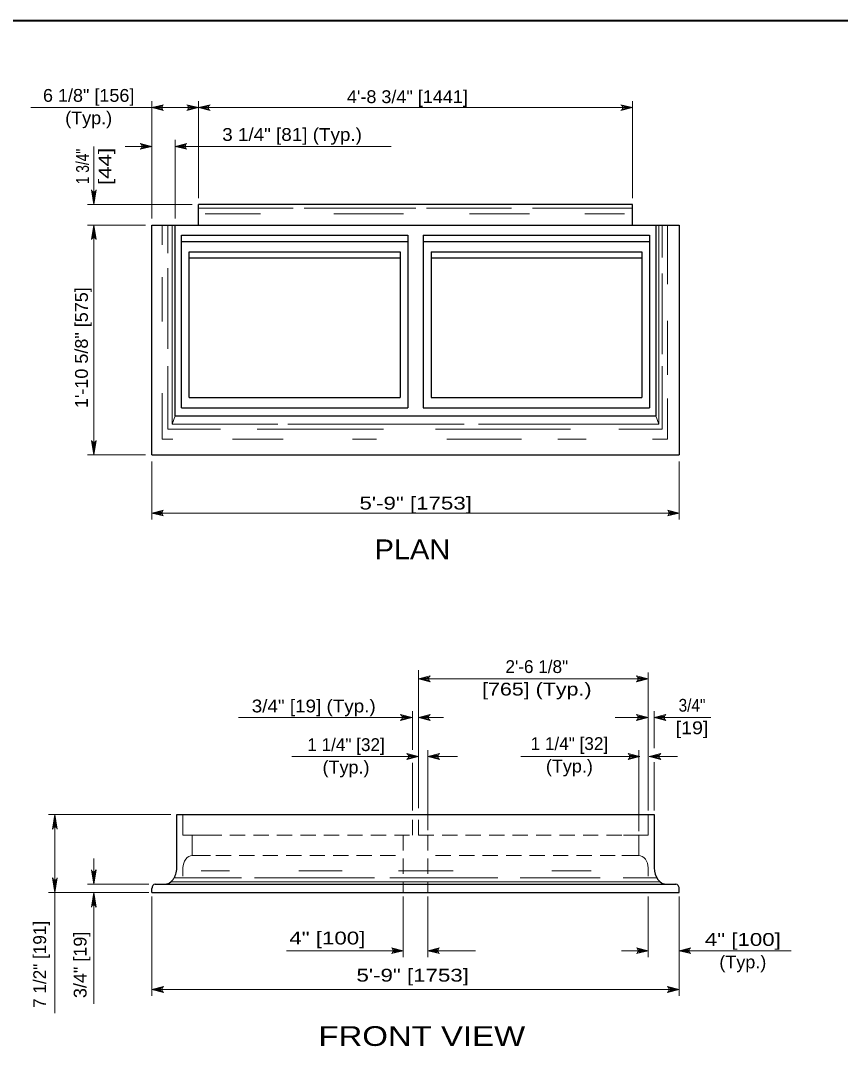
# Model space of a CAD drawing. Extents: x 1352.5 to 1386.5, y 735.9 to 779.9.
# Drawn here: x 1365.77 to 1375.75, y 744.93 to 757.42 of the extents above; entities that cross this region are included whole.
import ezdxf
from ezdxf.enums import TextEntityAlignment as Align

# ---------------------------------------------------------------- set-up
doc = ezdxf.new("R2010")
doc.units = 0
doc.header["$LTSCALE"] = 0.062
doc.linetypes.add('MEDIUM_DASHED', pattern=[4.5, 3, -1.5])
doc.layers.add('1', color=7, linetype='Continuous', lineweight=13)

msp = doc.modelspace()

# ---------------------------------------------------------------- linework, layer by layer
at = {"layer": '1', "lineweight": 25}
for p, q in [((1354.513, 757.41967), (1386.013, 757.41967)), ((1367.93525, 754.92942), (1367.93525, 755.17925)), ((1367.65208, 752.60575), (1367.65208, 754.92942)), ((1373.50492, 754.92942), (1373.50492, 752.60575)), ((1367.72758, 752.70567), (1367.72758, 754.80442)), ((1367.72758, 754.80442), (1370.48408, 754.80442)), ((1367.72758, 754.7295), (1370.48408, 754.7295)), ((1370.48408, 754.80442), (1370.48408, 752.70567)), ((1370.67292, 754.80442), (1370.67292, 752.70567)), ((1370.67292, 754.80442), (1373.42933, 754.80442)), ((1370.67292, 754.7295), (1373.42933, 754.7295)), ((1373.42933, 754.80442), (1373.42933, 752.70567)), ((1367.822, 752.83058), (1367.822, 754.60458)), ((1367.822, 754.60458), (1370.38967, 754.60458)), ((1370.38967, 754.60458), (1370.38967, 752.83058)), ((1370.76725, 754.60458), (1370.76725, 752.83058)), ((1370.76725, 754.60458), (1373.335, 754.60458)), ((1373.335, 754.60458), (1373.335, 752.83058)), ((1367.822, 754.52958), (1370.38967, 754.52958)), ((1370.76725, 754.52958), (1373.335, 754.52958)), ((1367.822, 752.83058), (1370.38967, 752.83058)), ((1370.76725, 752.83058), (1373.335, 752.83058)), ((1367.65208, 752.60575), (1373.50492, 752.60575)), ((1367.72758, 752.70567), (1370.48408, 752.70567)), ((1370.67292, 752.70567), (1373.42933, 752.70567)), ((1367.36892, 752.131), (1373.78808, 752.131)), ((1367.40667, 746.90283), (1373.75033, 746.90283)), ((1367.36892, 746.80292), (1367.36892, 746.85283)), ((1367.36892, 746.80292), (1373.78808, 746.80292)), ((1373.78808, 746.80292), (1373.78808, 746.85283))]:
    msp.add_line(p, q, dxfattribs=at)
at = {"layer": '1'}
for p, q in [((1367.36892, 756.35925), (1365.89425, 756.35925)), ((1367.36892, 755.00808), (1367.36892, 756.43792)), ((1367.49708, 756.38167), (1367.36892, 756.35925)), ((1367.49275, 756.37058), (1367.36892, 756.35925)), ((1367.49142, 756.35925), (1367.36892, 756.35925)), ((1367.49367, 756.34483), (1367.36892, 756.35925)), ((1367.49858, 756.3345), (1367.36892, 756.35925)), ((1373.22167, 756.35925), (1367.36892, 756.35925)), ((1367.7065, 756.35925), (1367.93525, 756.35925)), ((1367.80558, 756.3345), (1367.93525, 756.35925)), ((1367.80708, 756.38167), (1367.93525, 756.35925)), ((1367.8105, 756.34483), (1367.93525, 756.35925)), ((1367.81142, 756.37058), (1367.93525, 756.35925)), ((1367.81275, 756.35925), (1367.93525, 756.35925)), ((1367.93525, 755.25792), (1367.93525, 756.43792)), ((1368.0635, 756.38167), (1367.93525, 756.35925)), ((1368.05917, 756.37058), (1367.93525, 756.35925)), ((1368.05783, 756.35925), (1367.93525, 756.35925)), ((1368.06008, 756.34483), (1367.93525, 756.35925)), ((1368.065, 756.3345), (1367.93525, 756.35925)), ((1373.092, 756.3345), (1373.22167, 756.35925)), ((1373.0935, 756.38167), (1373.22167, 756.35925)), ((1373.09692, 756.34483), (1373.22167, 756.35925)), ((1373.09783, 756.37058), (1373.22167, 756.35925)), ((1373.09917, 756.35925), (1373.22167, 756.35925)), ((1373.22167, 755.25792), (1373.22167, 756.43792)), ((1366.66092, 755.17925), (1366.66092, 755.88725)), ((1366.66092, 755.17925), (1366.66092, 755.88725)), ((1367.36892, 755.88725), (1367.04092, 755.88725)), ((1367.23917, 755.8625), (1367.36892, 755.88725)), ((1367.24067, 755.90967), (1367.36892, 755.88725)), ((1367.24408, 755.87283), (1367.36892, 755.88725)), ((1367.245, 755.89858), (1367.36892, 755.88725)), ((1367.24633, 755.88725), (1367.36892, 755.88725)), ((1367.65208, 755.00808), (1367.65208, 755.96592)), ((1367.78025, 755.90967), (1367.65208, 755.88725)), ((1367.77592, 755.89858), (1367.65208, 755.88725)), ((1367.77458, 755.88725), (1367.65208, 755.88725)), ((1367.77692, 755.87283), (1367.65208, 755.88725)), ((1367.78175, 755.8625), (1367.65208, 755.88725)), ((1370.283, 755.88725), (1367.65208, 755.88725)), ((1366.64292, 755.3395), (1366.66092, 755.17925)), ((1366.65183, 755.33408), (1366.66092, 755.17925)), ((1366.68067, 755.34133), (1366.66092, 755.17925)), ((1366.67242, 755.33525), (1366.66092, 755.17925)), ((1366.66092, 755.33242), (1366.66092, 755.17925)), ((1367.85658, 755.17925), (1366.58225, 755.17925)), ((1369.08867, 755.13342), (1367.93525, 755.13342)), ((1370.58075, 755.13342), (1369.22075, 755.13342)), ((1371.748, 755.13342), (1370.71292, 755.13342)), ((1373.22167, 755.13342), (1372.00133, 755.13342)), ((1368.69217, 755.06783), (1368.01492, 755.06783)), ((1370.43208, 755.06783), (1369.58417, 755.06783)), ((1371.96833, 755.06783), (1371.236, 755.06783)), ((1373.12458, 755.06783), (1372.64008, 755.06783)), ((1367.29025, 754.92942), (1366.58225, 754.92942)), ((1366.64108, 754.76725), (1366.66092, 754.92942)), ((1366.64933, 754.77342), (1366.66092, 754.92942)), ((1366.66092, 754.77625), (1366.66092, 754.92942)), ((1366.66992, 754.77458), (1366.66092, 754.92942)), ((1366.67883, 754.76917), (1366.66092, 754.92942)), ((1366.66092, 752.131), (1366.66092, 754.92942)), ((1367.49183, 754.68892), (1367.49183, 754.92942)), ((1367.5635, 754.58692), (1367.5635, 754.92942)), ((1367.61433, 752.50575), (1367.61433, 754.92942)), ((1373.54267, 754.92942), (1373.54267, 752.50575)), ((1373.58158, 754.92942), (1373.58158, 754.53583)), ((1373.64758, 754.92942), (1373.64758, 754.208)), ((1367.5635, 753.421), (1367.5635, 754.40475)), ((1367.49183, 753.75625), (1367.49183, 754.29542)), ((1373.58158, 754.33917), (1373.58158, 753.35542)), ((1373.64758, 753.7635), (1373.64758, 753.10767)), ((1367.5635, 752.44467), (1367.5635, 753.20975)), ((1373.58158, 753.20975), (1373.58158, 752.44467)), ((1367.49183, 752.32075), (1367.49183, 752.88183)), ((1373.64758, 752.81625), (1373.64758, 752.32075)), ((1367.61433, 752.50575), (1367.65208, 752.60575)), ((1373.50492, 752.60575), (1373.54267, 752.50575)), ((1367.61433, 752.50575), (1368.90142, 752.50575)), ((1369.02258, 752.50575), (1371.16992, 752.50575)), ((1371.34608, 752.50575), (1373.54267, 752.50575)), ((1367.5635, 752.44467), (1368.20217, 752.44467)), ((1368.64817, 752.44467), (1370.18983, 752.44467)), ((1370.823, 752.44467), (1372.46383, 752.44467)), ((1373.05292, 752.44467), (1373.58158, 752.44467)), ((1366.64292, 752.29125), (1366.66092, 752.131)), ((1366.65183, 752.28583), (1366.66092, 752.131)), ((1366.68067, 752.29317), (1366.66092, 752.131)), ((1366.67242, 752.287), (1366.66092, 752.131)), ((1366.66092, 752.28417), (1366.66092, 752.131)), ((1367.49183, 752.32075), (1367.624, 752.32075)), ((1368.35083, 752.32075), (1368.9675, 752.32075)), ((1369.80992, 752.32075), (1370.10175, 752.32075)), ((1370.96067, 752.32075), (1371.86917, 752.32075)), ((1372.30967, 752.32075), (1372.6565, 752.32075)), ((1373.46592, 752.32075), (1373.64758, 752.32075)), ((1367.29025, 752.131), (1366.58225, 752.131)), ((1367.36892, 752.05233), (1367.36892, 751.34433)), ((1373.78808, 752.05233), (1373.78808, 751.34433)), ((1367.49708, 751.44542), (1367.36892, 751.423)), ((1367.49275, 751.43433), (1367.36892, 751.423)), ((1367.49142, 751.423), (1367.36892, 751.423)), ((1367.49367, 751.40858), (1367.36892, 751.423)), ((1367.49858, 751.39825), (1367.36892, 751.423)), ((1367.36892, 751.423), (1373.78808, 751.423)), ((1373.65842, 751.39825), (1373.78808, 751.423)), ((1373.65992, 751.44542), (1373.78808, 751.423)), ((1373.66325, 751.40858), (1373.78808, 751.423)), ((1373.66425, 751.43433), (1373.78808, 751.423)), ((1373.66558, 751.423), (1373.78808, 751.423)), ((1370.61625, 747.82967), (1370.61625, 749.51125)), ((1373.4105, 747.80233), (1373.4105, 749.483)), ((1370.74442, 749.42675), (1370.61625, 749.40433)), ((1370.74008, 749.41567), (1370.61625, 749.40433)), ((1370.61625, 749.40433), (1373.4105, 749.40433)), ((1370.73875, 749.40433), (1370.61625, 749.40433)), ((1370.741, 749.38992), (1370.61625, 749.40433)), ((1370.74592, 749.3795), (1370.61625, 749.40433)), ((1373.28075, 749.3795), (1373.4105, 749.40433)), ((1373.28225, 749.42675), (1373.4105, 749.40433)), ((1373.28567, 749.38992), (1373.4105, 749.40433)), ((1373.28667, 749.41567), (1373.4105, 749.40433)), ((1373.28792, 749.40433), (1373.4105, 749.40433)), ((1370.54075, 748.54208), (1370.54075, 749.01225)), ((1373.486, 748.56075), (1373.486, 749.01225)), ((1370.53858, 748.93358), (1368.42342, 748.93358)), ((1370.40892, 748.90875), (1370.53858, 748.93358)), ((1370.41042, 748.956), (1370.53858, 748.93358)), ((1370.41383, 748.91917), (1370.53858, 748.93358)), ((1370.41475, 748.94492), (1370.53858, 748.93358)), ((1370.41608, 748.93358), (1370.53858, 748.93358)), ((1370.74233, 748.956), (1370.61417, 748.93358)), ((1370.738, 748.94492), (1370.61417, 748.93358)), ((1370.73667, 748.93358), (1370.61417, 748.93358)), ((1370.73892, 748.91917), (1370.61417, 748.93358)), ((1370.74383, 748.90875), (1370.61417, 748.93358)), ((1370.61417, 748.93358), (1370.91725, 748.93358)), ((1373.41058, 748.93358), (1373.01058, 748.93358)), ((1373.28092, 748.90875), (1373.41058, 748.93358)), ((1373.28242, 748.956), (1373.41058, 748.93358)), ((1373.28583, 748.91917), (1373.41058, 748.93358)), ((1373.28675, 748.94492), (1373.41058, 748.93358)), ((1373.28808, 748.93358), (1373.41058, 748.93358)), ((1373.61433, 748.956), (1373.48608, 748.93358)), ((1373.61, 748.94492), (1373.48608, 748.93358)), ((1373.48608, 748.93358), (1374.17425, 748.93358)), ((1373.60867, 748.93358), (1373.48608, 748.93358)), ((1373.61092, 748.91917), (1373.48608, 748.93358)), ((1373.61583, 748.90875), (1373.48608, 748.93358)), ((1370.48808, 748.48058), (1370.61625, 748.45817)), ((1370.7295, 747.5635), (1370.7295, 748.53683)), ((1370.85775, 748.48058), (1370.7295, 748.45817)), ((1373.18167, 748.48058), (1373.30983, 748.45817)), ((1373.29717, 747.55033), (1373.29717, 748.53683)), ((1373.55133, 748.48058), (1373.42317, 748.45817)), ((1370.61625, 748.45817), (1369.07292, 748.45817)), ((1370.4865, 748.43342), (1370.61625, 748.45817)), ((1370.49142, 748.44375), (1370.61625, 748.45817)), ((1370.49242, 748.4695), (1370.61625, 748.45817)), ((1370.49375, 748.45817), (1370.61625, 748.45817)), ((1370.54075, 747.80233), (1370.54075, 748.38358)), ((1370.85333, 748.4695), (1370.7295, 748.45817)), ((1370.85208, 748.45817), (1370.7295, 748.45817)), ((1370.85433, 748.44375), (1370.7295, 748.45817)), ((1370.85925, 748.43342), (1370.7295, 748.45817)), ((1370.7295, 748.45817), (1371.08908, 748.45817)), ((1373.30983, 748.45817), (1371.86042, 748.45817)), ((1373.18017, 748.43342), (1373.30983, 748.45817)), ((1373.18508, 748.44375), (1373.30983, 748.45817)), ((1373.186, 748.4695), (1373.30983, 748.45817)), ((1373.18733, 748.45817), (1373.30983, 748.45817)), ((1373.547, 748.4695), (1373.42317, 748.45817)), ((1373.54567, 748.45817), (1373.42317, 748.45817)), ((1373.54792, 748.44375), (1373.42317, 748.45817)), ((1373.55283, 748.43342), (1373.42317, 748.45817)), ((1373.42317, 748.45817), (1373.76833, 748.45817)), ((1373.486, 747.80233), (1373.486, 748.38825)), ((1367.59825, 747.75233), (1366.10883, 747.75233)), ((1366.16767, 747.59025), (1366.1875, 747.75233)), ((1366.176, 747.59633), (1366.1875, 747.75233)), ((1366.1875, 747.59917), (1366.1875, 747.75233)), ((1366.19658, 747.5975), (1366.1875, 747.75233)), ((1366.20542, 747.59208), (1366.1875, 747.75233)), ((1373.4105, 747.75233), (1373.4105, 747.5025)), ((1373.4105, 747.5025), (1373.11075, 747.5025)), ((1373.29717, 747.5025), (1373.29717, 747.25267)), ((1367.85975, 747.25267), (1368.08108, 747.25267)), ((1373.29717, 747.25267), (1373.08992, 747.25267)), ((1366.65958, 746.90283), (1366.65958, 747.21675)), ((1366.64167, 747.06308), (1366.65958, 746.90283)), ((1366.6505, 747.05767), (1366.65958, 746.90283)), ((1366.67942, 747.065), (1366.65958, 746.90283)), ((1366.67108, 747.05883), (1366.65958, 746.90283)), ((1366.65958, 747.056), (1366.65958, 746.90283)), ((1367.63983, 746.98117), (1368.45858, 746.98117)), ((1367.96842, 747.06617), (1368.31267, 747.06617)), ((1368.61608, 746.98117), (1370.08058, 746.98117)), ((1369.15867, 747.06617), (1369.68383, 747.06617)), ((1370.26725, 746.98117), (1371.58017, 746.98117)), ((1370.37233, 747.06617), (1371.03742, 747.06617)), ((1371.85433, 746.98117), (1372.82875, 746.98117)), ((1372.23942, 747.06617), (1372.71792, 747.06617)), ((1373.10875, 746.98117), (1373.51708, 746.98117)), ((1366.16958, 746.96317), (1366.1875, 746.80292)), ((1366.17842, 746.95775), (1366.1875, 746.80292)), ((1366.20733, 746.965), (1366.1875, 746.80292)), ((1366.199, 746.95892), (1366.1875, 746.80292)), ((1366.1875, 746.95608), (1366.1875, 746.80292)), ((1367.33108, 746.90283), (1366.58225, 746.90283)), ((1367.602, 746.93492), (1373.555, 746.93492)), ((1367.33108, 746.80292), (1366.10883, 746.80292)), ((1366.63975, 746.64075), (1366.65958, 746.80292)), ((1366.64808, 746.64692), (1366.65958, 746.80292)), ((1366.65958, 746.80292), (1366.65958, 745.44633)), ((1366.65958, 746.64975), (1366.65958, 746.80292)), ((1366.66867, 746.64808), (1366.65958, 746.80292)), ((1366.6775, 746.64267), (1366.65958, 746.80292)), ((1367.36892, 745.54425), (1367.36892, 746.75292)), ((1370.42742, 746.01625), (1370.42742, 746.75292)), ((1370.7295, 746.01625), (1370.7295, 746.75292)), ((1373.4105, 746.01625), (1373.4105, 746.75292)), ((1373.78808, 745.54425), (1373.78808, 746.75292)), ((1370.29925, 746.11733), (1370.42742, 746.09492)), ((1370.30358, 746.10625), (1370.42742, 746.09492)), ((1370.85775, 746.11733), (1370.7295, 746.09492)), ((1370.85333, 746.10625), (1370.7295, 746.09492)), ((1373.28225, 746.11733), (1373.4105, 746.09492)), ((1373.28667, 746.10625), (1373.4105, 746.09492)), ((1373.91625, 746.11733), (1373.78808, 746.09492)), ((1373.91192, 746.10625), (1373.78808, 746.09492)), ((1369.008, 746.09492), (1370.42742, 746.09492)), ((1370.29775, 746.07008), (1370.42742, 746.09492)), ((1370.30267, 746.0805), (1370.42742, 746.09492)), ((1370.30492, 746.09492), (1370.42742, 746.09492)), ((1370.85208, 746.09492), (1370.7295, 746.09492)), ((1370.85433, 746.0805), (1370.7295, 746.09492)), ((1370.85925, 746.07008), (1370.7295, 746.09492)), ((1370.7295, 746.09492), (1371.31058, 746.09492)), ((1373.08783, 746.09492), (1373.4105, 746.09492)), ((1373.28075, 746.07008), (1373.4105, 746.09492)), ((1373.28567, 746.0805), (1373.4105, 746.09492)), ((1373.28792, 746.09492), (1373.4105, 746.09492)), ((1373.91058, 746.09492), (1373.78808, 746.09492)), ((1373.91292, 746.0805), (1373.78808, 746.09492)), ((1373.91775, 746.07008), (1373.78808, 746.09492)), ((1373.78808, 746.09492), (1375.15117, 746.09492)), ((1367.49708, 745.64533), (1367.36892, 745.62292)), ((1367.49275, 745.63425), (1367.36892, 745.62292)), ((1367.49142, 745.62292), (1367.36892, 745.62292)), ((1367.49367, 745.6085), (1367.36892, 745.62292)), ((1367.49858, 745.59808), (1367.36892, 745.62292)), ((1367.36892, 745.62292), (1373.78808, 745.62292)), ((1373.65842, 745.59808), (1373.78808, 745.62292)), ((1373.65992, 745.64533), (1373.78808, 745.62292)), ((1373.66325, 745.6085), (1373.78808, 745.62292)), ((1373.66425, 745.63425), (1373.78808, 745.62292)), ((1373.66558, 745.62292), (1373.78808, 745.62292))]:
    msp.add_line(p, q, dxfattribs=at)
at = {"layer": '1', "linetype": 'MEDIUM_DASHED'}
for p, q in [((1367.7465, 747.75233), (1367.7465, 747.5025)), ((1370.54075, 747.5025), (1370.54075, 747.75233)), ((1370.61625, 747.5025), (1370.61625, 747.75233)), ((1373.4105, 747.5025), (1373.4105, 747.75233)), ((1367.7465, 747.5025), (1370.54075, 747.5025)), ((1367.85975, 747.5025), (1367.85975, 747.25267)), ((1370.42742, 747.5025), (1370.42742, 746.80292)), ((1370.61625, 747.5025), (1373.4105, 747.5025)), ((1370.7295, 747.5025), (1370.7295, 746.80292)), ((1373.29717, 747.5025), (1373.29717, 747.25267)), ((1367.85975, 747.25267), (1370.42742, 747.25267)), ((1373.29717, 747.25267), (1370.7295, 747.25267)), ((1367.7465, 747.10275), (1367.7465, 747.00275)), ((1373.4105, 747.10275), (1373.4105, 747.00275))]:
    msp.add_line(p, q, dxfattribs=at)
at = {"layer": '1', "lineweight": 40}
msp.add_lwpolyline([(1354.513, 757.41967), (1386.013, 757.41967), (1386.013, 736.41967), (1354.513, 736.41967)], close=True, dxfattribs=at)
msp.add_lwpolyline([(1354.513, 757.41967), (1386.013, 757.41967), (1386.013, 736.41967), (1354.513, 736.41967)], close=True, dxfattribs=at)
at = {"layer": '1'}
for points in [[(1367.5105, 756.32383), (1367.36892, 756.35925), (1367.5105, 756.39467)], [(1367.79367, 756.32383), (1367.93525, 756.35925), (1367.79367, 756.39467)], [(1368.07692, 756.32383), (1367.93525, 756.35925), (1368.07692, 756.39467)], [(1373.08008, 756.32383), (1373.22167, 756.35925), (1373.08008, 756.39467)], [(1367.22725, 755.85183), (1367.36892, 755.88725), (1367.22725, 755.92267)], [(1367.79367, 755.85183), (1367.65208, 755.88725), (1367.79367, 755.92267)], [(1366.68917, 755.35625), (1366.66092, 755.17925), (1366.63258, 755.35625)], [(1366.63258, 754.75242), (1366.66092, 754.92942), (1366.68917, 754.75242)], [(1366.68917, 752.308), (1366.66092, 752.131), (1366.63258, 752.308)], [(1367.5105, 751.38758), (1367.36892, 751.423), (1367.5105, 751.45842)], [(1373.6465, 751.38758), (1373.78808, 751.423), (1373.6465, 751.45842)], [(1370.75783, 749.36892), (1370.61625, 749.40433), (1370.75783, 749.43967)], [(1373.26892, 749.36892), (1373.4105, 749.40433), (1373.26892, 749.43967)], [(1370.397, 748.89817), (1370.53858, 748.93358), (1370.397, 748.969)], [(1370.75575, 748.89817), (1370.61417, 748.93358), (1370.75575, 748.969)], [(1373.269, 748.89817), (1373.41058, 748.93358), (1373.269, 748.969)], [(1373.62775, 748.89817), (1373.48608, 748.93358), (1373.62775, 748.969)], [(1370.47467, 748.42275), (1370.61625, 748.45817), (1370.47467, 748.49358)], [(1370.87108, 748.42275), (1370.7295, 748.45817), (1370.87108, 748.49358)], [(1373.16825, 748.42275), (1373.30983, 748.45817), (1373.16825, 748.49358)], [(1373.56475, 748.42275), (1373.42317, 748.45817), (1373.56475, 748.49358)], [(1366.15917, 747.57533), (1366.1875, 747.75233), (1366.21583, 747.57533)], [(1366.1875, 745.33208), (1366.1875, 747.10492), (1366.1875, 747.75233)], [(1367.7465, 747.75233), (1367.7465, 747.5025), (1368.0465, 747.5025)], [(1367.85975, 747.5025), (1367.85975, 747.25267), (1367.94275, 747.25267)], [(1366.68792, 747.07983), (1366.65958, 746.90283), (1366.63125, 747.07983)], [(1366.21583, 746.97992), (1366.1875, 746.80292), (1366.15917, 746.97992)], [(1366.63125, 746.62592), (1366.65958, 746.80292), (1366.68792, 746.62592)], [(1370.28583, 746.0595), (1370.42742, 746.09492), (1370.28583, 746.13033)], [(1370.87108, 746.0595), (1370.7295, 746.09492), (1370.87108, 746.13033)], [(1373.26892, 746.0595), (1373.4105, 746.09492), (1373.26892, 746.13033)], [(1373.92967, 746.0595), (1373.78808, 746.09492), (1373.92967, 746.13033)], [(1367.5105, 745.5875), (1367.36892, 745.62292), (1367.5105, 745.65833)], [(1373.6465, 745.5875), (1373.78808, 745.62292), (1373.6465, 745.65833)]]:
    msp.add_lwpolyline(points, dxfattribs=at)
at = {"layer": '1', "lineweight": 25}
for points in [[(1373.22167, 754.92942), (1373.22167, 755.17925), (1367.93525, 755.17925)], [(1367.36892, 752.131), (1367.36892, 754.92942), (1373.78808, 754.92942), (1373.78808, 752.131)], [(1367.671, 747.10275), (1367.671, 747.75233), (1373.486, 747.75233), (1373.486, 747.10275)]]:
    msp.add_lwpolyline(points, dxfattribs=at)
at = {"layer": '1'}
for centre, major_axis, ratio, start_param, end_param in [((1367.52192, 756.35928), (0, 0.0382), 0.8, 0.38550522, 2.75611836), ((1367.78225, 756.35928), (0, 0.0382), 0.8, 3.52706694, 5.89768008), ((1368.08832, 756.35928), (0, 0.0382), 0.8, 0.38550522, 2.75611836), ((1373.06865, 756.35928), (0, 0.0382), 0.8, 3.52706694, 5.89768008), ((1367.21585, 755.88728), (0, 0.0382), 0.8, 3.52706694, 5.89768008), ((1367.80512, 755.88728), (0, 0.0382), 0.8, 0.38550522, 2.75611836), ((1366.66085, 755.37054), (0, -0.0382), 0.8, 5.0978942, 7.46850734), ((1366.66091, 754.73809), (0, 0.0382), 0.8, 5.0978942, 7.46850734), ((1366.66085, 752.32229), (0, -0.0382), 0.8, 5.0978942, 7.46850734), ((1367.52192, 751.42303), (0, 0.0382), 0.8, 0.38550522, 2.75611836), ((1373.63505, 751.42303), (0, 0.0382), 0.8, 3.52706694, 5.89768008), ((1370.76928, 749.40434), (0, 0.0382), 0.8, 0.38550522, 2.75611836), ((1373.25745, 749.40434), (0, 0.0382), 0.8, 3.52706694, 5.89768008), ((1370.38558, 748.93361), (0, 0.0382), 0.8, 3.52706694, 5.89768008), ((1370.76717, 748.93361), (0, 0.0382), 0.8, 0.38550522, 2.75611836), ((1373.25757, 748.93361), (0, 0.0382), 0.8, 3.52706694, 5.89768008), ((1373.63916, 748.93361), (0, 0.0382), 0.8, 0.38550522, 2.75611836), ((1370.46321, 748.45822), (0, 0.0382), 0.8, 3.52706694, 5.89768008), ((1370.88256, 748.45822), (0, 0.0382), 0.8, 0.38550522, 2.75611836), ((1373.15684, 748.45822), (0, 0.0382), 0.8, 3.52706694, 5.89768008), ((1373.57619, 748.45822), (0, 0.0382), 0.8, 0.38550522, 2.75611836), ((1366.18752, 747.56105), (0, 0.0382), 0.8, 5.0978942, 7.46850734), ((1367.85976, 747.10272), (0, 0.14991), 0.755635, 0, 1.57079633), ((1373.2972, 747.10272), (0, 0.14991), 0.755635, 4.71238898, 6.28318531), ((1366.65954, 747.09413), (0, -0.0382), 0.8, 5.0978942, 7.46850734), ((1366.18745, 746.99419), (0, -0.0382), 0.8, 5.0978942, 7.46850734), ((1366.6596, 746.6116), (0, 0.0382), 0.8, 5.0978942, 7.46850734), ((1370.27441, 746.09493), (0, 0.0382), 0.8, 3.52706694, 5.89768008), ((1370.88256, 746.09493), (0, 0.0382), 0.8, 0.38550522, 2.75611836), ((1373.25745, 746.09493), (0, 0.0382), 0.8, 3.52706694, 5.89768008), ((1373.94112, 746.09493), (0, 0.0382), 0.8, 0.38550522, 2.75611836), ((1367.52192, 745.62293), (0, 0.0382), 0.8, 0.38550522, 2.75611836), ((1373.63505, 745.62293), (0, 0.0382), 0.8, 3.52706694, 5.89768008)]:
    msp.add_ellipse(centre, major_axis=major_axis, ratio=ratio, start_param=start_param, end_param=end_param, dxfattribs=at)
at = {"layer": '1', "lineweight": 25}
for centre, major_axis, start_param, end_param in [((1367.51992, 747.10272), (0, 0.19988), 3.14159265, 4.71238898), ((1373.63704, 747.10272), (0, 0.19988), 1.57079633, 3.14159265), ((1367.40664, 746.85287), (0, 0.04997), 0, 1.57079633), ((1373.75032, 746.85287), (0, 0.04997), 4.71238898, 6.28318531)]:
    msp.add_ellipse(centre, major_axis=major_axis, ratio=0.755635, start_param=start_param, end_param=end_param, dxfattribs=at)

# ---------------------------------------------------------------- texts
at = {"layer": '1'}
for s, width, p in [('6 1/8" [156]', 1.05, (1366.59825, 756.42983)), ('(Typ.)', 1.05, (1366.59829, 756.15583)), ('[765] (Typ.)', 1.25, (1372.0555, 749.20142)), ('3/4" [19] (Typ.)', 1.1, (1369.33879, 748.99583)), ('3/4"', 0.9, (1373.94592, 749.0045)), ('[19]', 1.15, (1373.94587, 748.7305)), ('(Typ.)', 1.05, (1369.73212, 748.25142)), ('(Typ.)', 1.05, (1372.45246, 748.26408)), ('4" [100]', 1.3, (1374.56433, 746.15342)), ('(Typ.)', 1.05, (1374.56437, 745.87942))]:
    msp.add_text(s, height=0.156, dxfattribs=dict(at, width=width)).set_placement(p, align=Align.CENTER)
for s, height, width, p in [('4\'-8 3/4" [1441]', 0.156, 1.05, (1369.74367, 756.41433)), ('3 1/4" [81] (Typ.)', 0.156, 1.1, (1368.22458, 755.954)), ('5\'-9" [1753]', 0.156, 1.3, (1369.89567, 751.466)), ('PLAN', 0.24, 1.1, (1370.07958, 750.86142)), ('4" [100]', 0.156, 1.3, (1369.04175, 746.17067)), ('5\'-9" [1753]', 0.156, 1.3, (1369.85925, 745.71817)), ('FRONT VIEW', 0.24, 1.25, (1369.39567, 744.93533))]:
    msp.add_text(s, height=height, dxfattribs=dict(at, width=width)).set_placement(p)
for s, width, p in [('1 3/4"', 0.8, (1366.60175, 755.64254)), ('[44]', 1.3, (1366.87575, 755.6425))]:
    msp.add_text(s, height=0.156, rotation=90, dxfattribs=dict(at, width=width)).set_placement(p, align=Align.CENTER)
at = {"layer": '1', "width": 1.05}
for s, p in [('1\'-10 5/8" [575]', (1366.58858, 752.70092)), ('3/4" [19]', (1366.57208, 745.51767))]:
    msp.add_text(s, height=0.156, rotation=90, dxfattribs=at).set_placement(p)
at = {"layer": '1'}
for s, p in [('2\'-6 1/8"', (1372.05546, 749.47542)), ('1 1/4" [32]', (1369.73204, 748.52542)), ('1 1/4" [32]', (1372.45237, 748.53808))]:
    msp.add_text(s, height=0.156, dxfattribs=at).set_placement(p, align=Align.CENTER)
msp.add_text('7 1/2" [191]', height=0.156, rotation=90, dxfattribs=at).set_placement((1366.0795, 745.39792))

doc.saveas('drawing.dxf')
